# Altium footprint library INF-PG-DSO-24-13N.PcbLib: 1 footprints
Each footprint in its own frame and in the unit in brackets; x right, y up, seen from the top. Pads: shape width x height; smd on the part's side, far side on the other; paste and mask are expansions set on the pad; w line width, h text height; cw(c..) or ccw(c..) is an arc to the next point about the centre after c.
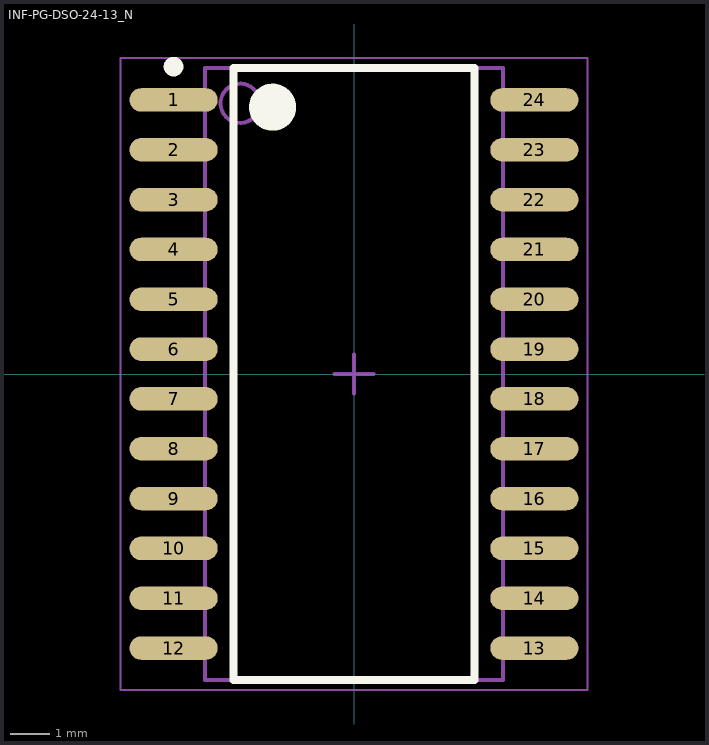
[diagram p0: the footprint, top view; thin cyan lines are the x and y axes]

## INF-PG-DSO-24-13_N [mm] "SOP, 24-Leads, Body 15.4x7.5mm, Pitch 1.27mm, IPC Medium Density"
height 2.65
pads (24):
  oval 2.25x0.6 smd: 1(-4.6,6.985) 2(-4.6,5.715) 3(-4.6,4.445) 4(-4.6,3.175) 5(-4.6,1.905) 6(-4.6,0.635) 7(-4.6,-0.635) 8(-4.6,-1.905) 9(-4.6,-3.175) 10(-4.6,-4.445) 11(-4.6,-5.715) 12(-4.6,-6.985) 13(4.6,-6.985) 14(4.6,-5.715) 15(4.6,-4.445) 16(4.6,-3.175) 17(4.6,-1.905) 18(4.6,-0.635) 19(4.6,0.635) 20(4.6,1.905) 21(4.6,3.175) 22(4.6,4.445) 23(4.6,5.715) 24(4.6,6.985)
Top Overlay:
  circle w0.25: c-4.6,7.835 r0.125
  circle w0.6: c-2.075,6.8 r0.3
  lines w0.2: -3.075,-7.8 -3.075,7.8 3.075,7.8 3.075,-7.8 -3.075,-7.8
Mechanical 13:
  circle w0.1: c-2.9,6.9 r0.5
  lines w0.1: -3.8,-7.8 -3.8,7.8 3.8,7.8 3.8,-7.8 -3.8,-7.8
Mechanical 15:
  lines w0.05: -5.95,-8.05 -5.95,8.05 5.95,8.05 5.95,-8.05 -5.95,-8.05
  lines w0.1: -0.5,0 0.5,0 ; 0,-0.5 0,0.5
3D body: height 2.65, standoff 0.1, extent -3.8,-7.8 3.8,7.8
